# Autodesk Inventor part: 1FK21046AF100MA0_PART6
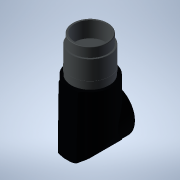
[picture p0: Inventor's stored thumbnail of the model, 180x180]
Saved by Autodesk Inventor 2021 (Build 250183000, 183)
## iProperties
Created: 2025-04
Part Number: 1FK21046AF100MA0_PART6
Material: Generic
Catalog Web Link: www.3dfindit.com
Description: -Servo synchronous motor
Document SubType Name: Modeling
Designer: psAdmin
Mass: 11.0817 g
Surface Area: 35.706 cm^2
Volume: 11.0817 cm^3
Density: 1 g/cm^3
Appearance: PSOLRGB-176-176-176
Category: PARTsolutions
Title: 1FK21046AF100MA0_PART6
Author: Cadenas PARTsolutions
Comments: Servo synchronous motor
Sending System: PARTsolutions
Preprocessor: ST-DEVELOPER v19.3
PSOL_IDENT_0: {$CADENAS_DATA/23d-libs/siemens_ag/_cat_/4f/2b/1fk21046af100ma0.prj},213 {VTYP=3D},{NB=1FK21046AF100
PSOL_IDENT_1: MA0_PART6},{LINA=1FK21046AF100MA0_PART6},{NN=1FK21046AF100MA0_PART6},{NOPRJ=TRUE},{DATE=19.08.2025 1
PSOL_IDENT_2: 4:00:37},{GEOMDATE=30.07.2025 02:01:06},{VERSION=},{LINEID=10},{WBVAR=},{WBNUMERIC=}  {NB=1FK21046AF
PSOL_IDENT_3: 100MA0_PART6},{LINA=1FK21046AF100MA0_PART6},{KT=DUMMY},{PREVIEW=../../../_pool_/cb/72/p_d211_xx_0043
PSOL_IDENT_4: 4j.png},{DESCSHORT=SIMOTICS S-1FK2 HD, SINAMICS S210 3AC 400V-480V, 3.2 Nm, 3000 rpm},{DESCLONG=SIMO
PSOL_IDENT_5: TICS S-1FK2 HD servo motor M0=3.2 Nm; PN = 1 kW at nN=3000 rpm (380-480 V); PN = 0.5 kW at nN=1500 r
PSOL_IDENT_6: pm (200-240 V); with holding brake; degree of protection IP64; cylindrical shaft D19x40mm; absolute
PSOL_IDENT_7: encoder 22-bit + 12-bit multiturn (encoder AM22DQC); with OCC interface; plug size M17, rotatable; S
PSOL_IDENT_8: IMOTICS S-1FK2 servomotorfor a wide range of uses in industrial environments. SIMOTICS S‑1FK2 servom
PSOL_IDENT_9: otors are compact synchronous motors with a high dynamic performance that set themselves apart as a
PSOL_IDENT_10: result of their high power density, degree of protection and overload capability. The motors are ava
PSOL_IDENT_11: ilable in two variants: as High Dynamic variant (highest dynamic performance as a result of the low
PSOL_IDENT_12: intrinsic moment of inertia for applications demanding a high dynamic performance with low moved mas
PSOL_IDENT_13: ses) - and as Compact variant (precise and stable closed-loop control for medium up to large moved m
PSOL_IDENT_14: asses as a result of a medium intrinsic moment of inertia). SIMOTICSS‑1FK2 servomotors fully exploit
PSOL_IDENT_15: their strengths in a system with the SINAMICSS210 frequency converter and simple connection using t
PSOL_IDENT_16: he one cable connection (OCC). Advantages include the short control and positioning times, fast and
PSOL_IDENT_17: precise correction of disturbing quantities as well as stable control with a high dynamic performanc
PSOL_IDENT_18: e. The servo motors can be configured to address a wide range of requirements. For example with and
PSOL_IDENT_19: without holding brake, IP64 or IP65 degree of protection, singleturn or multiturn absolute encoders
PSOL_IDENT_20: - to name just a few. Further, the servomotors are available in different shaft heights extending fr
PSOL_IDENT_21: om 20 to 100. A shaft sealing ring is available to achieve an IP65 degree of protection and for subs
PSOL_IDENT_22: equent mounting at the motor or as spare part. SIMOTICS - the optimum motor for each and every motio
PSOL_IDENT_23: n control application.},{INTNO=195125049673},{SUPPLIERALTNO=1FK2104-6AF10-0MA0},{MANUID=1FK21046AF10
PSOL_IDENT_24: 0MA0},{MANUNAME=Siemens},{MANUTYPEDESC=Synchronous motor 1FK2-HD 3.2 NM},{AAU732=SIMOTICS},{AAO057=S
PSOL_IDENT_25: -1FK2},{AAU734=SIMOTICS S-1FK2 HD servo motor M0=3.2 Nm; PN = 1 kW at nN=3000 rpm (380-480 V); PN =
PSOL_IDENT_26: 0.5 kW at nN=1500 rpm (200-240 V); with holding brake; degree of protection IP64; cylindrical shaft
PSOL_IDENT_27: D19x40mm; absolute encoder 22-bit + 12-bit multiturn (encoder AM22DQC); with OCC interface; plug siz
PSOL_IDENT_28: e M17, rotatable;},{AAW338=Synchronous motor 1FK2-HD 3.2 NM},{AAO742=SIMOTICS},{AAO663=4042948694534
PSOL_IDENT_29: },{NOCUPEROU=1},{PRICEQUANTITY=1},{QUANTITYMIN=1},{QUANTITYINT=1},{CTN=85015220},{COO=DE},{AAO676=1F
PSOL_IDENT_30: K2104-6AF10-0MA0},{AAO677=Siemens AG},{ORDERUNIT=C62},{CONTENTUNIT=C62}
NB: 1FK21046AF100MA0_PART6
NT: Servo synchronous motor
NBSYN: $MANUID._PART6
LINA: 1FK21046AF100MA0_PART6
CATALOG: SIEMENS
PREVIEW: ../../../_pool_/cb/72/p_d211_xx_00434j.png
DESCSHORT: SIMOTICS S-1FK2 HD, SINAMICS S210 3AC 400V-480V, 3.2 Nm, 3000 rpm
DESCLONG: SIMOTICS S-1FK2 HD servo motor M0=3.2 Nm; PN = 1 kW at nN=3000 rpm (380-480 V); PN = 0.5 kW at nN=1500 rpm (200-240 V); with holding brake; degree of protection
INTNO: 195125049673
SUPPLIERALTNO: 1FK2104-6AF10-0MA0
MANUID: 1FK21046AF100MA0
MANUNAME: Siemens
MANUTYPEDESC: Synchronous motor 1FK2-HD 3.2 NM
AAU732: SIMOTICS
AAO057: S-1FK2
AAU734: SIMOTICS S-1FK2 HD servo motor M0=3.2 Nm; PN = 1 kW at nN=3000 rpm (380-480 V); PN = 0.5 kW at nN=1500 rpm (200-240 V); with holding brake; degree of protection
AAW338: Synchronous motor 1FK2-HD 3.2 NM
AAO742: SIMOTICS
AAO663: 4042948694534.0
NOCUPEROU: 1
PRICEQUANTITY: 1
QUANTITYMIN: 1
QUANTITYINT: 1
CTN: 85015220
COO: DE
ARTICLENO: 1FK21046AF100MA0_PART6
BOMINFO: 1FK21046AF100MA0_PART6
CREATOR: CADENAS GmbH
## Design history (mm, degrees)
feature "2025_04_17_14_59_39_0146"
body "Solid1"
